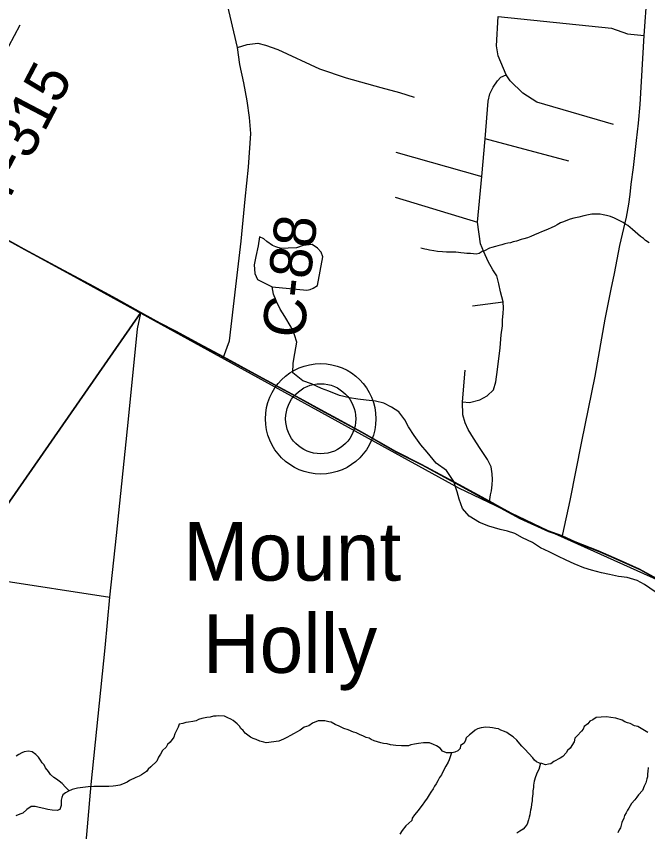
# Model space of a CAD drawing. Extents: x 0 to 39.3, y -3.9 to 22.
# Drawn here: x 6.099 to 6.949, y 16.679 to 17.777 of the extents above; entities that cross this region are included whole.
import ezdxf

# ---------------------------------------------------------------- set-up
doc = ezdxf.new("R2010")
doc.units = 0
for name, color, linetype in [('GM_X_Corporation', 7, 'Continuous'), ('GM_X_County_Road', 7, 'Continuous'), ('GM_X_County_Road_Text', 7, 'Continuous'), ('GM_X_Minor_Lake', 7, 'Continuous'), ('GM_X_Minor_River', 7, 'Continuous'), ('GM_X_Rail_Line', 7, 'Continuous'), ('GM_X_State_Route', 7, 'Continuous'), ('GM_X_Township_Road', 7, 'Continuous'), ('GM_X_Township_Road_Text', 7, 'Continuous'), ('GM_X_Unincorporated', 7, 'Continuous'), ('GM_X_Unincorporated_Location', 7, 'Continuous'), ('GM_X_Unincorporated_Text', 7, 'Continuous')]:
    doc.layers.add(name, color=color, linetype=linetype)

msp = doc.modelspace()

# ---------------------------------------------------------------- linework, layer by layer
at = {"layer": 'GM_X_Corporation'}
for points in [[(6.0256, 17.0319), (6.2667, 17.3782), (6.2343, 17.3967), (6.1976, 17.4164), (6.1575, 17.438), (6.1099, 17.4635), (6.0756, 17.4827)], [(6.0756, 17.4827), (6.1099, 17.4635), (6.1575, 17.438), (6.1976, 17.4164), (6.2343, 17.3967), (6.2667, 17.3782), (6.2927, 17.3642), (6.3138, 17.353), (6.3454, 17.3362), (6.3781, 17.3188), (6.4308, 17.2899), (6.4814, 17.2624), (6.5093, 17.2471), (6.5366, 17.2326), (6.5646, 17.2171), (6.6103, 17.1913), (6.6449, 17.1735), (6.6951, 17.1465), (6.7363, 17.1241), (6.7556, 17.1133), (6.7773, 17.1016), (6.8155, 17.0842), (6.8341, 17.0776), (6.8518, 17.0697), (6.8828, 17.0574), (6.9113, 17.0449), (6.9385, 17.0327), (6.9679, 17.0164)], [(6.9679, 17.0164), (6.9385, 17.0327), (6.9113, 17.0449), (6.8828, 17.0574), (6.8518, 17.0697), (6.8341, 17.0776), (6.8155, 17.0842), (6.7773, 17.1016), (6.7556, 17.1133), (6.7363, 17.1241), (6.6951, 17.1465), (6.6449, 17.1735), (6.6103, 17.1913), (6.5646, 17.2171), (6.5366, 17.2326), (6.5093, 17.2471), (6.4814, 17.2624), (6.4308, 17.2899), (6.3781, 17.3188), (6.3454, 17.3362), (6.3138, 17.353), (6.2927, 17.3642), (6.2667, 17.3782), (6.0256, 17.0319)]]:
    msp.add_lwpolyline(points, dxfattribs=at)
at = {"layer": 'GM_X_County_Road'}
for points in [[(6.3783, 17.3183), (6.3863, 17.3402), (6.395, 17.4132), (6.4018, 17.4743), (6.4076, 17.5311), (6.4119, 17.5741), (6.4149, 17.6194), (6.4133, 17.6408), (6.41, 17.6636), (6.4057, 17.6877), (6.4, 17.7123), (6.3969, 17.7352), (6.3824, 17.7985), (6.3718, 17.8456), (6.369, 17.8578), (6.3627, 17.8852), (6.3225, 18.0398), (6.2916, 18.1689), (6.2686, 18.277), (6.2623, 18.3053), (6.2601, 18.3244), (6.2604, 18.3439), (6.3029, 18.7216)], [(6.7775, 16.4687), (6.7555, 16.4724), (6.6671, 16.4823), (6.4045, 16.5144), (6.3754, 16.5183), (6.3437, 16.5225), (6.3203, 16.5247), (6.3095, 16.5263), (6.2855, 16.5361), (6.2304, 16.5573), (6.1919, 16.5725), (6.1845, 16.5782), (6.1899, 16.6288), (6.2, 16.7428), (6.219, 16.9267), (6.2251, 16.9948), (6.2341, 17.078), (6.2503, 17.2345), (6.2622, 17.3562), (6.267, 17.3776)]]:
    msp.add_lwpolyline(points, dxfattribs=at)
at = {"layer": 'GM_X_Minor_Lake'}
for points in [[(6.4268, 17.4803), (6.4247, 17.4681), (6.4218, 17.4538), (6.4197, 17.4424), (6.4206, 17.431), (6.4239, 17.4229), (6.4439, 17.4127)], [(6.4439, 17.4127), (6.4906, 17.4085), (6.4951, 17.4091), (6.499, 17.411), (6.5047, 17.4147), (6.5119, 17.4533), (6.5097, 17.4595), (6.5048, 17.4649), (6.4977, 17.4699), (6.4855, 17.4686), (6.4767, 17.4653), (6.4653, 17.4648), (6.4558, 17.4646), (6.4486, 17.467), (6.4441, 17.4686), (6.4365, 17.474), (6.4324, 17.4775), (6.4268, 17.4803)]]:
    msp.add_lwpolyline(points, dxfattribs=at)
at = {"layer": 'GM_X_Minor_River'}
for points in [[(6.9516, 17.472), (6.9467, 17.4752), (6.9437, 17.4779), (6.9399, 17.4806), (6.9362, 17.4837), (6.9324, 17.4872), (6.9291, 17.4903), (6.9257, 17.493), (6.9227, 17.4954), (6.9197, 17.4973), (6.9163, 17.4997), (6.905, 17.5052), (6.8993, 17.5076), (6.894, 17.5088), (6.8895, 17.51), (6.8857, 17.5108), (6.8819, 17.5109), (6.8781, 17.5106), (6.8743, 17.5107), (6.8697, 17.51), (6.8636, 17.5086), (6.8567, 17.5068), (6.8502, 17.5054), (6.8449, 17.504), (6.8415, 17.5029), (6.8361, 17.5003), (6.8319, 17.4989)], [(6.8319, 17.4989), (6.8277, 17.4963), (6.8242, 17.4948), (6.8196, 17.4922), (6.8154, 17.4904), (6.81, 17.4882), (6.8066, 17.4871), (6.8024, 17.4853), (6.797, 17.4831), (6.792, 17.4809), (6.7878, 17.4787), (6.7825, 17.4777), (6.779, 17.4766), (6.7729, 17.4744), (6.7683, 17.4733), (6.7645, 17.4723), (6.7611, 17.4716), (6.7569, 17.4709), (6.7531, 17.4694), (6.7477, 17.468), (6.7447, 17.4673), (6.7397, 17.4659), (6.7366, 17.4648), (6.7297, 17.4615), (6.7267, 17.4604), (6.7225, 17.4578), (6.7183, 17.4567), (6.7148, 17.4572), (6.7107, 17.4576), (6.7057, 17.4577), (6.7023, 17.4581), (6.6978, 17.4586), (6.6947, 17.459), (6.6909, 17.4595), (6.6784, 17.4597), (6.6731, 17.4602), (6.6662, 17.4607), (6.6613, 17.4615), (6.6556, 17.4624), (6.6522, 17.4632), (6.6492, 17.4636), (6.6439, 17.4649)], [(6.9597, 17.0023), (6.9454, 17.0121), (6.9352, 17.0172), (6.922, 17.0216), (6.9102, 17.0229), (6.8981, 17.0254), (6.8871, 17.0279), (6.8738, 17.0312), (6.8633, 17.0344), (6.8504, 17.0399), (6.8395, 17.0447), (6.8285, 17.0502), (6.8169, 17.0561), (6.8052, 17.0616), (6.7943, 17.0687), (6.7811, 17.075), (6.7705, 17.0805), (6.7607, 17.0837), (6.7508, 17.0861), (6.7357, 17.0906), (6.7229, 17.0957), (6.7089, 17.104), (6.7, 17.1144), (6.6956, 17.127), (6.6931, 17.1369), (6.6884, 17.1507), (6.6784, 17.1657), (6.6645, 17.1754), (6.6526, 17.1901), (6.644, 17.2001), (6.6351, 17.2125), (6.6273, 17.2244), (6.6226, 17.234), (6.6144, 17.2447), (6.6046, 17.251), (6.594, 17.2561), (6.5827, 17.259), (6.5705, 17.2603), (6.5592, 17.2617), (6.5478, 17.2634), (6.5345, 17.2667), (6.5202, 17.2726), (6.51, 17.2762), (6.4968, 17.2821), (6.4851, 17.2861), (6.4715, 17.297), (6.4718, 17.3099), (6.4743, 17.3232), (6.4768, 17.3384), (6.4739, 17.3483), (6.4692, 17.3587), (6.4607, 17.3729), (6.4544, 17.3829), (6.4496, 17.3932), (6.4456, 17.4032), (6.4439, 17.4127)], [(6.6181, 16.7947), (6.6102, 16.7952), (6.603, 16.7961), (6.5984, 16.7973), (6.5939, 16.7981), (6.5901, 16.799), (6.581, 16.8014), (6.5772, 16.8034), (6.5742, 16.805), (6.5704, 16.8058), (6.5659, 16.8081), (6.5621, 16.8094), (6.5569, 16.8121), (6.5531, 16.8133), (6.5463, 16.8165), (6.5402, 16.8181), (6.5368, 16.8197), (6.5338, 16.8213), (6.5285, 16.8236), (6.5233, 16.8264), (6.5202, 16.8272), (6.5145, 16.8285), (6.5111, 16.8285), (6.5058, 16.8282), (6.4981, 16.8253), (6.4931, 16.8216), (6.487, 16.8198), (6.4813, 16.8157), (6.4766, 16.8131), (6.4732, 16.8113), (6.4674, 16.808), (6.4644, 16.8065), (6.459, 16.8036), (6.4525, 16.801), (6.4357, 16.799), (6.4323, 16.7995), (6.427, 16.8011), (6.4221, 16.8031), (6.418, 16.8047), (6.4146, 16.8062), (6.4074, 16.8117), (6.4048, 16.8152), (6.4015, 16.8183), (6.3996, 16.8213), (6.3966, 16.8244), (6.3914, 16.8287), (6.388, 16.8307), (6.3842, 16.8323), (6.3797, 16.8346), (6.3717, 16.8351), (6.3683, 16.8348), (6.3649, 16.8345), (6.3603, 16.8334), (6.3557, 16.8328), (6.3488, 16.8314), (6.3446, 16.8303), (6.3412, 16.8285), (6.337, 16.8274), (6.3309, 16.8264), (6.3275, 16.826), (6.3233, 16.825), (6.3187, 16.8239), (6.3171, 16.8198), (6.3128, 16.8111), (6.3115, 16.8065), (6.3065, 16.7998), (6.303, 16.7964), (6.3011, 16.793), (6.296, 16.7885), (6.2933, 16.7836), (6.2906, 16.7795), (6.2882, 16.7742), (6.2805, 16.7664), (6.2766, 16.7634), (6.2743, 16.76), (6.2677, 16.7556), (6.2647, 16.7537), (6.2601, 16.7519), (6.2516, 16.7479), (6.2486, 16.7456), (6.2451, 16.7446), (6.242, 16.7431), (6.2386, 16.742), (6.2333, 16.741), (6.2295, 16.7406), (6.2237, 16.74), (6.2127, 16.7402), (6.2089, 16.7399), (6.2036, 16.74), (6.196, 16.7397), (6.1853, 16.7384), (6.1815, 16.7377), (6.1781, 16.737), (6.1743, 16.7359), (6.1693, 16.7337), (6.1654, 16.7315), (6.162, 16.7289), (6.1604, 16.7251), (6.1596, 16.7217), (6.1594, 16.7145), (6.1578, 16.7088)], [(6.9496, 16.8128), (6.9454, 16.8152), (6.9405, 16.8179), (6.9364, 16.821), (6.9319, 16.8219), (6.9258, 16.8247), (6.9224, 16.8259), (6.9187, 16.8271), (6.9153, 16.8294), (6.9066, 16.8322), (6.8997, 16.8331), (6.894, 16.8336), (6.8868, 16.8333), (6.8803, 16.8327), (6.8754, 16.8297), (6.8715, 16.8279), (6.8688, 16.8245), (6.8638, 16.8208), (6.8626, 16.8174), (6.8603, 16.8144), (6.8545, 16.8084), (6.8514, 16.805), (6.8505, 16.8001), (6.8451, 16.7918), (6.8416, 16.7885), (6.8396, 16.7851), (6.8354, 16.7802), (6.8315, 16.778), (6.8231, 16.7736), (6.8189, 16.7706), (6.8158, 16.7699), (6.812, 16.7692), (6.8071, 16.7708), (6.8037, 16.7716), (6.7999, 16.7732), (6.7969, 16.7756), (6.795, 16.7786), (6.7838, 16.7902), (6.7801, 16.7945), (6.7775, 16.7976), (6.7734, 16.8022), (6.7685, 16.8069), (6.7632, 16.81), (6.7599, 16.8127), (6.7565, 16.8139), (6.7519, 16.8159), (6.7485, 16.8175), (6.7448, 16.8179), (6.7406, 16.8192), (6.7368, 16.8196), (6.7315, 16.8197), (6.7254, 16.819), (6.7204, 16.8176), (6.717, 16.8158), (6.7135, 16.8128), (6.7096, 16.8094), (6.705, 16.8057), (6.7042, 16.8023), (6.7022, 16.7985), (6.6976, 16.7952), (6.6968, 16.791), (6.6937, 16.788), (6.6899, 16.7862), (6.686, 16.7851), (6.6784, 16.7852), (6.6731, 16.7876), (6.6698, 16.7915), (6.6649, 16.7946), (6.6608, 16.7966), (6.6555, 16.7986), (6.652, 16.7986), (6.6475, 16.7987), (6.641, 16.7981), (6.6353, 16.797), (6.6307, 16.796), (6.6273, 16.7949), (6.6242, 16.7946), (6.6181, 16.7947)], [(6.1704, 16.7342), (6.1656, 16.7391), (6.1607, 16.7441), (6.157, 16.7472), (6.1532, 16.75), (6.1498, 16.7523), (6.1453, 16.7562), (6.1424, 16.7604), (6.1386, 16.7651), (6.1368, 16.7693), (6.1338, 16.772), (6.1316, 16.7755), (6.129, 16.7793), (6.1256, 16.7832), (6.1207, 16.7867), (6.1154, 16.7875), (6.1097, 16.7865), (6.1067, 16.7854), (6.1024, 16.7832), (6.099, 16.781)], [(6.6852, 16.7851), (6.6821, 16.7757), (6.6809, 16.7727), (6.6778, 16.7674), (6.6758, 16.764), (6.6719, 16.7557), (6.6691, 16.7523), (6.6668, 16.7478), (6.6648, 16.7436), (6.6625, 16.7403), (6.6605, 16.7369), (6.6574, 16.7324), (6.655, 16.7286), (6.6523, 16.7241), (6.6488, 16.7192), (6.6457, 16.7147), (6.6426, 16.7109), (6.6402, 16.7076), (6.6356, 16.7016), (6.6325, 16.6974), (6.6317, 16.6944), (6.6239, 16.6869), (6.6189, 16.6809), (6.6158, 16.6757)], [(6.8052, 16.7713), (6.8031, 16.7629), (6.8008, 16.7588), (6.7984, 16.7531), (6.7968, 16.747), (6.7959, 16.7417), (6.7955, 16.7387), (6.795, 16.7341), (6.7946, 16.7303), (6.7942, 16.7269), (6.7941, 16.7239), (6.7937, 16.7208), (6.7932, 16.7163), (6.7924, 16.7114), (6.7916, 16.7083), (6.7911, 16.7053), (6.7907, 16.7019), (6.7899, 16.6988), (6.7891, 16.6951), (6.7871, 16.6894), (6.7843, 16.6856), (6.7816, 16.6826), (6.7774, 16.68), (6.7732, 16.6771)], [(6.9499, 16.7657), (6.9495, 16.76), (6.9494, 16.7569), (6.949, 16.7531), (6.9485, 16.7501), (6.9469, 16.7448), (6.9449, 16.7403), (6.9426, 16.7346), (6.9371, 16.7286), (6.9348, 16.7256), (6.9321, 16.7222), (6.9278, 16.717), (6.9239, 16.7109), (6.9223, 16.7079), (6.9204, 16.7045), (6.9184, 16.7008), (6.9172, 16.6974), (6.9148, 16.6913), (6.9128, 16.6845), (6.9109, 16.6815), (6.9093, 16.6777)], [(6.1578, 16.7088), (6.1544, 16.7077), (6.1476, 16.7079), (6.1415, 16.7091), (6.1381, 16.7099), (6.1282, 16.712), (6.1245, 16.7132), (6.1191, 16.7129), (6.1134, 16.7092), (6.1079, 16.704), (6.1037, 16.7025), (6.0984, 16.7003)]]:
    msp.add_lwpolyline(points, dxfattribs=at)
at = {"layer": 'GM_X_Rail_Line'}
msp.add_lwpolyline([(5.9832, 17.5323), (6.1809, 17.4246), (6.6945, 17.1424), (6.8149, 17.0848), (6.966, 17.0168), (7.0746, 16.9262), (7.1215, 16.9012), (7.4207, 16.8333), (7.4717, 16.8224), (7.5307, 16.8022), (7.5779, 16.7788), (7.8941, 16.5999)], dxfattribs=at)
at = {"layer": 'GM_X_State_Route'}
for points in [[(6.8343, 17.077), (6.835, 17.0798), (6.8452, 17.1251), (6.8606, 17.2046), (6.8786, 17.2928), (6.8923, 17.3692), (6.9002, 17.4098), (6.9049, 17.4307), (6.9119, 17.4684), (6.9208, 17.5068), (6.9241, 17.5244), (6.9257, 17.5373), (6.9271, 17.5514), (6.9305, 17.5735), (6.9344, 17.6101), (6.937, 17.6333), (6.9392, 17.6583), (6.9449, 17.7512), (6.9489, 17.8075)], [(5.9798, 17.5338), (6.0062, 17.5197), (6.0381, 17.5022), (6.0583, 17.4914), (6.0758, 17.4822), (6.1101, 17.463), (6.1577, 17.4375), (6.1978, 17.4158), (6.2346, 17.3962), (6.267, 17.3776)], [(6.267, 17.3776), (6.293, 17.3637), (6.314, 17.3525), (6.3457, 17.3357), (6.3783, 17.3183), (6.431, 17.2894), (6.4817, 17.2619), (6.5095, 17.2466)], [(6.5095, 17.2466), (6.5368, 17.2321), (6.5649, 17.2166), (6.6105, 17.1908), (6.6451, 17.173), (6.6954, 17.1459), (6.7366, 17.1235), (6.7559, 17.1128), (6.7775, 17.1011), (6.8158, 17.0836), (6.8343, 17.077)], [(6.8343, 17.077), (6.852, 17.0692), (6.883, 17.0569), (6.8996, 17.0497)], [(6.8996, 17.0497), (6.9116, 17.0444), (6.9388, 17.0322), (6.9681, 17.0159), (6.9893, 17.0016), (7.0008, 16.9929), (7.0065, 16.9881), (7.0153, 16.9804), (7.0277, 16.9702)]]:
    msp.add_lwpolyline(points, dxfattribs=at)
at = {"layer": 'GM_X_Township_Road'}
for p, q in [((5.9798, 17.5338), (6.1044, 17.7657)), ((6.8434, 17.5823), (6.7307, 17.6124)), ((6.6103, 17.5944), (6.726, 17.5613)), ((6.6094, 17.5337), (6.7204, 17.5)), ((6.7136, 17.3874), (6.755, 17.3929)), ((6.0562, 17.021), (6.2251, 16.9948))]:
    msp.add_line(p, q, dxfattribs=at)
for points in [[(6.9036, 17.6314), (6.8004, 17.6614), (6.7815, 17.6736), (6.7643, 17.6905), (6.7589, 17.6984), (6.7479, 17.724), (6.7457, 17.7377), (6.7479, 17.7771), (6.9008, 17.7614), (6.9221, 17.7535), (6.9449, 17.7512)], [(6.3969, 17.7352), (6.4101, 17.7392), (6.4246, 17.7409), (6.4346, 17.7384), (6.4514, 17.7326), (6.5074, 17.7065), (6.5433, 17.6943), (6.5899, 17.6814), (6.6154, 17.6748), (6.6352, 17.6685)], [(6.7, 17.2579), (6.7095, 17.2572), (6.7235, 17.2606), (6.7334, 17.2662), (6.7418, 17.2741), (6.7449, 17.2848), (6.7471, 17.3018), (6.7509, 17.3307), (6.7523, 17.3484), (6.7538, 17.3604), (6.754, 17.3685), (6.755, 17.3769), (6.7552, 17.3841), (6.755, 17.3929), (6.7514, 17.4061), (6.749, 17.417), (6.7461, 17.4276), (6.7408, 17.4357), (6.7346, 17.4472), (6.7289, 17.4601), (6.7241, 17.4706), (6.7204, 17.5), (6.726, 17.5613), (6.7307, 17.6124), (6.7347, 17.6629), (6.7367, 17.6728), (6.7415, 17.6819), (6.7471, 17.6904), (6.7519, 17.6953), (6.7589, 17.6984)], [(6.7366, 17.1235), (6.7379, 17.1328), (6.7392, 17.1382), (6.74, 17.1463), (6.7407, 17.1536), (6.7402, 17.1612), (6.7387, 17.1703), (6.7337, 17.1802), (6.7239, 17.1951), (6.7148, 17.2092), (6.7076, 17.2209), (6.7035, 17.2296), (6.7004, 17.2405), (6.7, 17.2579), (6.7037, 17.3006)]]:
    msp.add_lwpolyline(points, dxfattribs=at)
at = {"layer": 'GM_X_Unincorporated'}
for radius in [0.0744, 0.0472]:
    msp.add_circle((6.5091, 17.2352), radius, dxfattribs=at)
at = {"layer": 'GM_X_Unincorporated_Location'}
msp.add_line((6.5091, 17.2352), (6.5091, 17.2352), dxfattribs=at)

# ---------------------------------------------------------------- texts
at = {"layer": 'GM_X_County_Road_Text'}
msp.add_text('C-88', height=0.05682, rotation=83.5233, dxfattribs=at).set_placement((6.4862, 17.3422))
at = {"layer": 'GM_X_Township_Road_Text'}
msp.add_text('T-315', height=0.05682, rotation=62.3064, dxfattribs=at).set_placement((6.0837, 17.5189))
at = {"layer": 'GM_X_Unincorporated_Text'}
for s, p in [('Mount', (6.3239, 17.0172)), ('Holly', (6.3506, 16.893))]:
    msp.add_text(s, height=0.07898, rotation=0, dxfattribs=at).set_placement(p)

doc.saveas('drawing.dxf')
